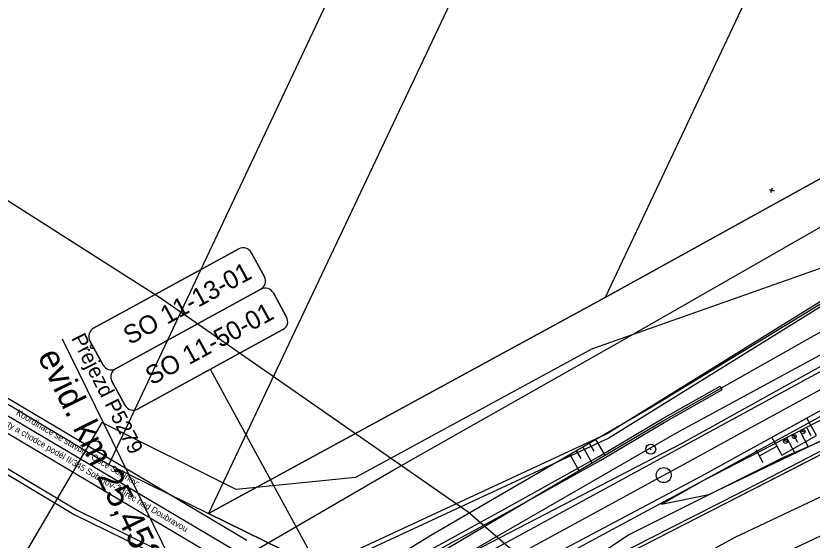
# Model space of a CAD drawing. Extents: x -9100 to -8660, y -10901 to -10569.
# Drawn here: x -8996.5 to -8916.9, y -10775.6 to -10723.3 of the extents above; entities that cross this region are included whole.
import ezdxf

# ---------------------------------------------------------------- set-up
doc = ezdxf.new("R2010")
doc.units = 0
for name, color, linetype in [('01_CETIN - STP nezaměřená poloha', 7, 'Continuous'), ('16_SSZT', 7, 'Continuous'), ('16_SSZT - DK', 7, 'Continuous'), ('17_ČD - telematika', 7, 'Continuous'), ('bubliny', 7, 'Continuous'), ('C3D-TRASA', 7, 'Continuous'), ('HranDP', 7, 'Continuous'), ('Hranice parcel', 7, 'Continuous'), ('JC - SITU - Silnice', 7, 'Continuous'), ('SDĚL__BUBLINY', 7, 'Continuous'), ('Vnitřní kresba', 7, 'Continuous'), ('Vrstva 1', 7, 'Continuous'), ('Vrstva 4', 7, 'Continuous'), ('Vrstva 48', 7, 'Continuous'), ('Vrstva 49', 7, 'Continuous'), ('Vrstva 7', 7, 'Continuous')]:
    doc.layers.add(name, color=color, linetype=linetype)

msp = doc.modelspace()

# ---------------------------------------------------------------- linework, layer by layer
at = {"layer": '01_CETIN - STP nezaměřená poloha'}
msp.add_lwpolyline([(-9016.625, -10729.424), (-8982.024, -10751.442), (-8951.263, -10772.823), (-8941.735, -10781.043), (-8912.892, -10798.946), (-8905.964, -10823.272), (-8913.115, -10836.635), (-8914.038, -10838.212)], dxfattribs=at)
at = {"layer": '16_SSZT'}
for points in [[(-9074.585, -10817.612), (-9054.624, -10814.278), (-9033.944, -10809.249), (-9016.331, -10803.227), (-8993.207, -10794.934), (-8992.236, -10796.991), (-8989.816, -10802.65), (-8978.528, -10800.389), (-8972.071, -10800.763), (-8969.887, -10800.323), (-8960.588, -10792.058), (-8935.292, -10775.141), (-8919.684, -10767.375), (-8910.065, -10763.204), (-8903.876, -10759.887), (-8899.774, -10757.335), (-8892.343, -10752.193), (-8875.762, -10743.528)], [(-8898.973, -10756.95), (-8902.242, -10756.235), (-8903.938, -10756.596), (-8906.578, -10758.251), (-8908.097, -10761.436), (-8909.812, -10763.554), (-8921.931, -10769.83), (-8933.078, -10775.478), (-8951.398, -10784.881), (-8963.08, -10790.024), (-8966.715, -10791.759), (-8974.833, -10795.863), (-8979.944, -10798.857)]]:
    msp.add_lwpolyline(points, dxfattribs=at)
at = {"layer": '16_SSZT - DK'}
msp.add_lwpolyline([(-8978.528, -10800.389), (-8972.071, -10800.763), (-8969.887, -10800.323), (-8960.588, -10792.058), (-8935.292, -10775.141), (-8919.684, -10767.375), (-8910.065, -10763.204), (-8903.876, -10759.887), (-8899.774, -10757.335), (-8892.343, -10752.193), (-8875.762, -10743.528)], dxfattribs=at)
at = {"layer": '17_ČD - telematika'}
for p, q in [((-8938.781, -10756.517), (-8907.851, -10745.568)), ((-8938.781, -10756.517), (-8962.511, -10769.392)), ((-8987.88, -10763.89), (-9003.057, -10789.767)), ((-8974.452, -10770.575), (-8987.88, -10763.89)), ((-8962.511, -10769.392), (-8974.452, -10770.575))]:
    msp.add_line(p, q, dxfattribs=at)
for points in [[(-8978.528, -10800.389), (-8972.071, -10800.763), (-8969.887, -10800.323), (-8960.588, -10792.058), (-8935.292, -10775.141), (-8919.684, -10767.375), (-8910.065, -10763.204), (-8903.876, -10759.887), (-8899.774, -10757.335), (-8892.343, -10752.193), (-8875.762, -10743.528)], [(-8973.866, -10800.284), (-8973.203, -10800.546), (-8973.06, -10800.825), (-8972.46, -10801.12), (-8969.887, -10800.323), (-8960.588, -10792.058), (-8935.292, -10775.141), (-8919.684, -10767.375), (-8910.065, -10763.204), (-8903.876, -10759.887), (-8899.774, -10757.335), (-8892.343, -10752.193), (-8879.745, -10745.609)]]:
    msp.add_lwpolyline(points, dxfattribs=at)
at = {"layer": 'bubliny'}
for points in [[(-8974.182, -10746.544), (-8988.711, -10754.482)], [(-8971.611, -10749.332), (-8972.934, -10746.91)], [(-8986.506, -10758.518), (-8971.977, -10750.58)], [(-8971.976, -10750.58), (-8986.505, -10758.518)], [(-8969.405, -10753.367), (-8970.728, -10750.946)], [(-8984.3, -10762.553), (-8969.771, -10754.615)], [(-8989.077, -10755.73), (-8987.754, -10758.152)], [(-8986.871, -10759.766), (-8985.548, -10762.187)]]:
    msp.add_lwpolyline(points, dxfattribs=at)
for centre, start, end in [((-8973.741, -10747.351), 28.65046, 118.65046), ((-8972.418, -10749.773), 298.65046, 28.65046), ((-8971.535, -10751.387), 28.65046, 118.65046), ((-8970.212, -10753.808), 298.65046, 28.65046), ((-8988.27, -10755.289), 118.65046, 208.65046), ((-8986.947, -10757.711), 208.65046, 298.65046), ((-8986.064, -10759.325), 118.65046, 208.65046), ((-8984.741, -10761.746), 208.65046, 298.65046)]:
    msp.add_arc(centre, 0.92, start, end, dxfattribs=at)
at = {"layer": 'C3D-TRASA'}
msp.add_line((-9032.282, -10742.537), (-8974.144, -10776.933), dxfattribs=at)
at = {"layer": 'HranDP'}
for p, q in [((-8937.546, -10751.419), (-8889.026, -10724.57)), ((-8977.199, -10772.987), (-8937.546, -10751.419)), ((-8896.281, -10757.034), (-8947.729, -10783.331)), ((-8965.614, -10778.66), (-8977.199, -10772.987))]:
    msp.add_line(p, q, dxfattribs=at)
at = {"layer": 'Hranice parcel'}
for p, q in [((-8932.837, -10679.264), (-8977.199, -10772.987)), ((-8906.911, -10686.517), (-8937.546, -10751.419)), ((-8949.578, -10688.411), (-8987.187, -10768.093)), ((-8889.026, -10724.57), (-8937.546, -10751.419)), ((-8937.546, -10751.419), (-8977.199, -10772.987)), ((-8987.187, -10768.093), (-8977.199, -10772.987)), ((-8977.199, -10772.987), (-8965.614, -10778.66))]:
    msp.add_line(p, q, dxfattribs=at)
for points in [[(-8881.284, -10733.421), (-8906.791, -10746.989), (-8907.913, -10745.543), (-8912.442, -10748.102), (-8911.552, -10749.582), (-8937.178, -10765.452), (-8965.614, -10778.66)], [(-9038.922, -10737.225), (-9022.634, -10746.912), (-8987.187, -10768.093)], [(-9045.036, -10740.565), (-9025.707, -10752.068), (-8990.653, -10773.077), (-8972.614, -10781.915)], [(-8874.914, -10745.08), (-8896.281, -10757.034), (-8947.729, -10783.331)], [(-8920.572, -10777.384), (-8874.784, -10755.67), (-8870.651, -10752.882)]]:
    msp.add_lwpolyline(points, dxfattribs=at)
at = {"layer": 'JC - SITU - Silnice'}
for p, q in [((-9031.518, -10741.246), (-8973.38, -10775.642)), ((-9033.045, -10743.828), (-8974.908, -10778.224)), ((-8926.064, -10760.274), (-8925.872, -10760.625))]:
    msp.add_line(p, q, dxfattribs=at)
for points in [[(-8958.292, -10778.443), (-8955.65, -10776.956), (-8953.5, -10775.781), (-8951.279, -10774.563), (-8946.91, -10772.154), (-8942.542, -10769.735), (-8938.173, -10767.309), (-8931.855, -10763.54), (-8926.064, -10760.274)], [(-8958.103, -10778.796), (-8955.461, -10777.308), (-8953.31, -10776.133), (-8951.088, -10774.914), (-8946.719, -10772.506), (-8942.35, -10770.086), (-8937.981, -10767.66), (-8931.659, -10763.888), (-8925.872, -10760.625)]]:
    msp.add_lwpolyline(points, dxfattribs=at)
at = {"layer": 'SDĚL__BUBLINY'}
for p, q in [((-8988.712, -10754.483), (-8974.182, -10746.544)), ((-8972.934, -10746.91), (-8971.611, -10749.332)), ((-8971.977, -10750.58), (-8986.507, -10758.519)), ((-8986.506, -10758.518), (-8971.976, -10750.58)), ((-8970.728, -10750.946), (-8969.405, -10753.368)), ((-8969.771, -10754.616), (-8984.301, -10762.554)), ((-8987.755, -10758.153), (-8989.078, -10755.731)), ((-8977.036, -10758.584), (-8962.572, -10785.058)), ((-8985.549, -10762.188), (-8986.872, -10759.766))]:
    msp.add_line(p, q, dxfattribs=at)
for centre, start, end in [((-8973.741, -10747.351), 28.65001, 118.65001), ((-8972.418, -10749.773), 298.65001, 28.65001), ((-8971.535, -10751.387), 28.65001, 118.65001), ((-8970.212, -10753.809), 298.65001, 28.65001), ((-8988.271, -10755.29), 118.65001, 208.65001), ((-8986.948, -10757.712), 208.65001, 298.65001), ((-8986.065, -10759.325), 118.65001, 208.65001), ((-8984.742, -10761.747), 208.65001, 298.65001)]:
    msp.add_arc(centre, 0.92, start, end, dxfattribs=at)
at = {"layer": 'Vnitřní kresba'}
for p, q in [((-8937.414, -10765.015), (-8912.233, -10749.421)), ((-9025.456, -10751.64), (-8990.419, -10772.635)), ((-8965.828, -10778.207), (-8937.414, -10765.015)), ((-8990.419, -10772.635), (-8972.613, -10781.364))]:
    msp.add_line(p, q, dxfattribs=at)
at = {"layer": 'Vrstva 1'}
msp.add_lwpolyline([(-9071.078, -10824.031), (-9068.55, -10823.67), (-9059.39, -10822.051), (-9049.732, -10820.012), (-9040.576, -10817.765), (-9031.032, -10815.085), (-9021.565, -10812.071), (-9019.212, -10811.266), (-9010.687, -10808.158), (-9001.881, -10804.632), (-8992.751, -10800.668), (-8983.884, -10796.567), (-8979.025, -10794.235), (-8968.639, -10789.006), (-8963.908, -10786.557), (-8955.013, -10781.841), (-8946.607, -10777.298), (-8938.34, -10772.786), (-8931.689, -10769.156), (-8930.764, -10768.65), (-8923.574, -10764.727), (-8915.206, -10760.16)], dxfattribs=at)
at = {"layer": 'Vrstva 4'}
msp.add_line((-8974.037, -10791.724), (-8991.814, -10755.583), dxfattribs=at)
for points in [[(-8878.837, -10737.9), (-8884.05, -10740.755), (-8907.714, -10753.704), (-8929.956, -10766.035), (-8953.482, -10778.221), (-8969.174, -10786.201), (-8971.356, -10786.933), (-8970.433, -10787.575), (-8968.68, -10786.636), (-8952.884, -10778.842), (-8929.737, -10766.245), (-8907.522, -10754.16), (-8883.768, -10741.075), (-8878.641, -10738.258)], [(-8877.029, -10741.209), (-8882.153, -10744.006), (-8905.333, -10756.826), (-8927.898, -10769.268), (-8951.338, -10781.689), (-8966.191, -10789.81), (-8967.491, -10790.487)], [(-8967.491, -10790.487), (-8965.547, -10790.154), (-8951.016, -10782.224), (-8927.695, -10769.647), (-8905.236, -10757.41), (-8902.231, -10755.792), (-8881.893, -10744.368), (-8876.806, -10741.618)]]:
    msp.add_lwpolyline(points, dxfattribs=at)
at = {"layer": 'Vrstva 48'}
for p, q in [((-8917.399, -10764.371), (-8916.983, -10765.183)), ((-8918.734, -10765.055), (-8918.327, -10765.849)), ((-8918.066, -10764.713), (-8917.243, -10766.319)), ((-8939.148, -10765.962), (-8938.691, -10766.75)), ((-8938.499, -10765.585), (-8937.587, -10767.156)), ((-8919.401, -10765.397), (-8918.597, -10766.967)), ((-8940.445, -10766.715), (-8939.985, -10767.507)), ((-8939.796, -10766.338), (-8938.879, -10767.919)), ((-8941.094, -10767.091), (-8940.171, -10768.681))]:
    msp.add_line(p, q, dxfattribs=at)
at = {"layer": 'Vrstva 49'}
for p, q in [((-8920.971, -10740.922), (-8920.83, -10740.443)), ((-8921.14, -10740.612), (-8920.661, -10740.753))]:
    msp.add_line(p, q, dxfattribs=at)
for points in [[(-8978.662, -10780.206), (-8958.735, -10768.644), (-8935.621, -10755.565), (-8884.993, -10726.632)], [(-8953.482, -10778.221), (-8930.419, -10764.92), (-8908.933, -10753.298), (-8906.21, -10751.88), (-8884.466, -10739.975), (-8879.257, -10737.132)], [(-8944.942, -10804.675), (-8947.817, -10788.104), (-8924.546, -10775.35), (-8902.033, -10764.739), (-8899.648, -10763.338), (-8873.387, -10748.479), (-8873.131, -10748.344)], [(-8978.662, -10780.206), (-8972.308, -10784.335), (-8970.493, -10784.578), (-8969.357, -10784.006), (-8954.982, -10775.152), (-8933.011, -10762.4), (-8911.309, -10749.16), (-8911, -10749.364), (-8910.159, -10750.652), (-8909.705, -10751.264)], [(-8979.617, -10781.869), (-8973.485, -10785.447), (-8971.382, -10786.114), (-8969.484, -10785.715), (-8953.993, -10776.842), (-8931.757, -10763.714), (-8909.746, -10751.3), (-8909.705, -10751.264)], [(-8931.928, -10772.047), (-8927.695, -10769.647), (-8906.039, -10758.55), (-8905.826, -10758.103), (-8905.071, -10760.022), (-8905.014, -10760.2)], [(-8931.928, -10772.047), (-8927.196, -10771.086), (-8905.229, -10760.564), (-8905.014, -10760.2)]]:
    msp.add_lwpolyline(points, dxfattribs=at)
at = {"layer": 'Vrstva 7'}
for p, q in [((-8918.443, -10765.352), (-8918.823, -10765.243)), ((-8917.567, -10764.859), (-8917.948, -10764.75)), ((-8919.318, -10765.84), (-8919.698, -10765.731)), ((-8933.038, -10766.581), (-8932.951, -10766.533)), ((-8922.494, -10766.585), (-8921.766, -10767.897))]:
    msp.add_line(p, q, dxfattribs=at)
msp.add_lwpolyline([(-8922.13, -10767.241), (-8920.382, -10766.27), (-8919.896, -10767.145), (-8916.399, -10765.204), (-8917.369, -10763.455), (-8920.867, -10765.396), (-8920.382, -10766.27)], dxfattribs=at)
for centre, radius in [((-8918.633, -10765.3), 0.2), ((-8917.759, -10764.815), 0.2), ((-8932.994, -10766.557), 0.5), ((-8919.507, -10765.785), 0.2), ((-8931.689, -10769.156), 0.75)]:
    msp.add_circle(centre, radius, dxfattribs=at)

# ---------------------------------------------------------------- texts
at = {"layer": 'JC - SITU - Silnice'}
for s, p in [('Stezka pro cyklisty a chodce podél II/345 Sobíňov-Ždírec nad Doubravou', (-9002.768, -10761.1)), ('Koordinace se stavbou Obce Sobiňov:', (-8996.519, -10763.077))]:
    msp.add_text(s, height=0.625, rotation=329.39001, dxfattribs=at).set_placement(p)
at = {"layer": 'SDĚL__BUBLINY'}
for s, p in [('SO 11-13-01', (-8985.088, -10756.172)), ('SO 11-50-01', (-8982.883, -10760.207))]:
    msp.add_text(s, height=1.83967, rotation=28.65002, dxfattribs=at).set_placement(p)
at = {"layer": 'Vrstva 4'}
for s, height, rotation, p in [('Přejezd P5279', 1.5, 296.8694, (-8990.971, -10755.467)), ('evid. km 25,452', 2.5, 296.19191, (-8994.353, -10757.265))]:
    msp.add_text(s, height=height, rotation=rotation, dxfattribs=at).set_placement(p)

doc.saveas('drawing.dxf')
